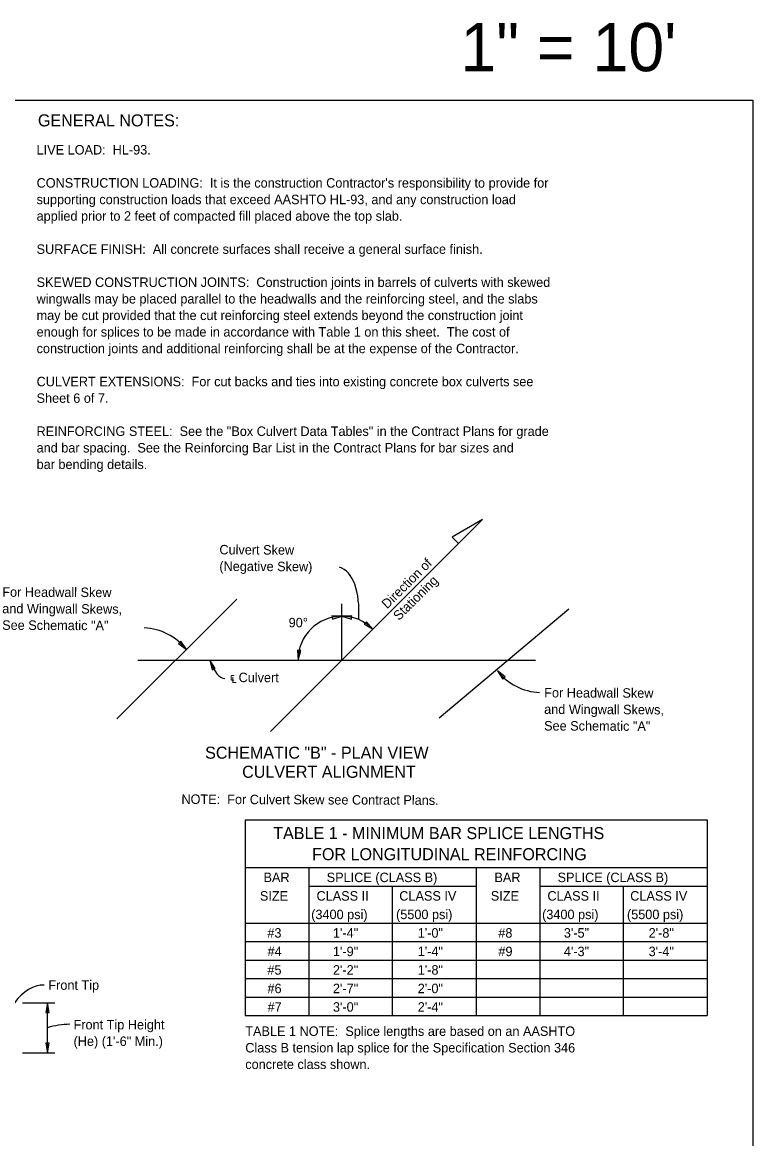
# Model space of a CAD drawing. Extents: x 6 to 291, y -45 to 111.
# Drawn here: x 101.7 to 159.9, y 22.3 to 111.3 of the extents above; entities that cross this region are included whole.
import ezdxf

# ---------------------------------------------------------------- set-up
doc = ezdxf.new("R2010")
doc.units = 0
for name, color, linetype in [('ActivePts-ConstElements', 7, 'Continuous'), ('AdhocPoint_dp', 7, 'Continuous'), ('CL_Minor', 7, 'Continuous'), ('Leader', 7, 'Continuous'), ('PlotBorder_dp', 7, 'Continuous'), ('SubStrConc', 7, 'Continuous'), ('Tables', 7, 'Continuous')]:
    doc.layers.add(name, color=color, linetype=linetype)

msp = doc.modelspace()

# ---------------------------------------------------------------- linework, layer by layer
at = {"layer": 'ActivePts-ConstElements'}
msp.add_lwpolyline([(5.513, 105.087), (159.887, 105.087), (159.887, 6.648), (5.513, 6.648)], close=True, dxfattribs=at)
at = {"layer": 'AdhocPoint_dp'}
msp.add_line((138.359, 71.665), (121.444, 54.75), dxfattribs=at)
msp.add_lwpolyline([(138.359, 71.665), (135.932, 70.255), (136.441, 69.747)], close=True, dxfattribs=at)
at = {"layer": 'CL_Minor'}
msp.add_line((110.873, 60.443), (142.578, 60.443), dxfattribs=at)
at = {"layer": 'Leader'}
msp.add_line((127.137, 60.443), (127.137, 64.939), dxfattribs=at)
for centre, radius, start, end in [((111.176, 58.492), 4.533, 38.2591, 87.41318), ((143.098, 62.394), 4.533, 218.2591, 267.41318), ((105.498, 25.127), 6.283, 90.41603, 107.01592)]:
    msp.add_arc(centre, radius, start, end, dxfattribs=at)
for centre, major_axis, ratio, start_param, end_param in [((125.161, 61.66), (-1.787, -6.198), 0.454139, 2.029538, 3.141593), ((117.704, 65.904), (-0.102, 6.91), 0.278379, 2.477956, 3.141593), ((103.368, 27.495), (-0.033, -7.044), 0.555933, 3.141593, 3.786656)]:
    msp.add_ellipse(centre, major_axis=major_axis, ratio=ratio, start_param=start_param, end_param=end_param, dxfattribs=at)
at = {"layer": 'PlotBorder_dp'}
for p, q in [((101.666, 33.134), (104.257, 33.134)), ((103.659, 29.134), (103.659, 33.134)), ((101.666, 29.134), (104.257, 29.134))]:
    msp.add_line(p, q, dxfattribs=at)
for points in [[(127.137, 63.944), (126.346, 63.988), (126.376, 63.725)], [(127.137, 63.944), (127.899, 63.726), (127.928, 63.989)], [(129.612, 62.918), (129.089, 63.513), (128.922, 63.308)], [(114.735, 61.299), (114.305, 61.965), (114.11, 61.786)], [(123.637, 60.443), (123.851, 61.206), (123.588, 61.234)], [(116.6, 60.443), (116.793, 59.675), (117.035, 59.782)], [(139.539, 59.587), (139.972, 58.924), (140.167, 59.104)], [(103.659, 33.134), (103.527, 32.353), (103.792, 32.353)], [(103.659, 29.134), (103.792, 29.915), (103.527, 29.915)]]:
    msp.add_lwpolyline(points, close=True, dxfattribs=at)
for start, end in [(90, 180), (45.00012, 90)]:
    msp.add_arc((127.137, 60.443), 3.5, start, end, dxfattribs=at)
at = {"layer": 'SubStrConc'}
for p, q in [((118.755, 65.319), (109.203, 55.768)), ((145.23, 64.5), (134.882, 55.817))]:
    msp.add_line(p, q, dxfattribs=at)
at = {"layer": 'Tables'}
for p, q in [((119.434, 47.722), (119.434, 32.1)), ((119.434, 47.722), (156.254, 47.722)), ((156.254, 47.722), (156.254, 32.1)), ((119.434, 43.908), (156.254, 43.908)), ((124.504, 43.908), (124.504, 32.1)), ((137.844, 43.908), (137.844, 32.1)), ((142.914, 43.908), (142.914, 32.1)), ((124.504, 42.432), (137.844, 42.432)), ((131.148, 42.432), (131.148, 32.1)), ((142.914, 42.432), (142.914, 32.1)), ((142.914, 42.432), (156.254, 42.432)), ((149.558, 42.432), (149.558, 32.1)), ((119.434, 39.48), (156.254, 39.48)), ((119.434, 38.004), (156.254, 38.004)), ((119.434, 36.528), (156.254, 36.528)), ((119.434, 35.052), (156.254, 35.052)), ((119.434, 33.576), (156.254, 33.576)), ((119.434, 32.1), (156.254, 32.1))]:
    msp.add_line(p, q, dxfattribs=at)

# ---------------------------------------------------------------- texts
at = {"layer": 'AdhocPoint_dp'}
for s, height, p in [('1" = 10\'', 3.84, (136.588, 107.409)), ('GENERAL NOTES:', 0.96, (102.901, 103.009)), ('LIVE LOAD:  HL-93.', 0.756, (102.795, 100.765)), ("CONSTRUCTION LOADING:  It is the construction Contractor's responsibility to provide for", 0.756, (102.795, 98.125)), ('supporting construction loads that exceed AASHTO HL-93, and any construction load', 0.756, (102.795, 96.805)), ('applied prior to 2 feet of compacted fill placed above the top slab.', 0.756, (102.795, 95.485)), ('SURFACE FINISH:  All concrete surfaces shall receive a general surface finish.', 0.756, (102.795, 92.845)), ('SKEWED CONSTRUCTION JOINTS:  Construction joints in barrels of culverts with skewed', 0.756, (102.795, 90.205)), ('wingwalls may be placed parallel to the headwalls and the reinforcing steel, and the slabs', 0.756, (102.795, 88.885)), ('may be cut provided that the cut reinforcing steel extends beyond the construction joint', 0.756, (102.795, 87.565)), ('enough for splices to be made in accordance with Table 1 on this sheet.  The cost of', 0.756, (102.795, 86.245)), ('construction joints and additional reinforcing shall be at the expense of the Contractor.', 0.756, (102.795, 84.925)), ('CULVERT EXTENSIONS:  For cut backs and ties into existing concrete box culverts see', 0.756, (102.795, 82.285)), ('Sheet 6 of 7.', 0.756, (102.795, 80.965)), ('REINFORCING STEEL:  See the "Box Culvert Data Tables" in the Contract Plans for grade', 0.756, (102.795, 78.325)), ('and bar spacing.  See the Reinforcing Bar List in the Contract Plans for bar sizes and', 0.756, (102.795, 77.005)), ('bar bending details.', 0.756, (102.795, 75.685)), ('SCHEMATIC "B" - PLAN VIEW', 0.96, (116.233, 52.588)), ('CULVERT ALIGNMENT', 0.96, (119.184, 51.064)), ('TABLE 1 - MINIMUM BAR SPLICE LENGTHS', 0.96, (121.661, 46.175)), ('FOR LONGITUDINAL REINFORCING', 0.96, (124.76, 44.495)), ('BAR', 0.756, (120.889, 42.748)), ('SPLICE (CLASS B)', 0.756, (125.924, 42.748)), ('BAR', 0.756, (139.299, 42.748)), ('SPLICE (CLASS B)', 0.756, (144.334, 42.748)), ('SIZE', 0.756, (120.598, 41.272)), ('CLASS II', 0.756, (125.114, 41.272)), ('CLASS IV', 0.756, (131.712, 41.272)), ('SIZE', 0.756, (139.008, 41.272)), ('CLASS II', 0.756, (143.524, 41.272)), ('CLASS IV', 0.756, (150.124, 41.272)), ('(3400 psi)', 0.756, (124.689, 39.796)), ('(5500 psi)', 0.756, (131.453, 39.796)), ('(3400 psi)', 0.756, (143.099, 39.796)), ('(5500 psi)', 0.756, (149.864, 39.796)), ('#3', 0.756, (121.194, 38.32)), ('1\'-4"', 0.756, (126.422, 38.32)), ('1\'-0"', 0.756, (133.184, 38.32)), ('#8', 0.756, (139.607, 38.32)), ('3\'-5"', 0.756, (144.832, 38.32)), ('2\'-8"', 0.756, (151.595, 38.32)), ('#4', 0.756, (121.21, 36.844)), ('1\'-9"', 0.756, (126.422, 36.844)), ('1\'-4"', 0.756, (133.184, 36.844)), ('#9', 0.756, (139.613, 36.844)), ('4\'-3"', 0.756, (144.832, 36.844)), ('3\'-4"', 0.756, (151.595, 36.844)), ('#5', 0.756, (121.198, 35.368)), ('2\'-2"', 0.756, (126.422, 35.368)), ('1\'-8"', 0.756, (133.184, 35.368)), ('Front Tip', 0.756, (103.735, 34.16)), ('#6', 0.756, (121.203, 33.892)), ('2\'-7"', 0.756, (126.422, 33.892)), ('2\'-0"', 0.756, (133.184, 33.892)), ('#7', 0.756, (121.212, 32.416)), ('3\'-0"', 0.756, (126.422, 32.416)), ('2\'-4"', 0.756, (133.184, 32.416)), ('Front Tip Height', 0.756, (105.743, 31.004)), ('TABLE 1 NOTE:  Splice lengths are based on an AASHTO', 0.756, (119.434, 30.484)), ('(He) (1\'-6" Min.)', 0.756, (105.743, 29.684)), ('Class B tension lap splice for the Specification Section 346', 0.756, (119.434, 29.164)), ('concrete class shown.', 0.756, (119.434, 27.844))]:
    msp.add_text(s, height=height, dxfattribs=at).set_placement(p)
for s, rotation, p in [('Culvert Skew', 359.76619, (117.371, 68.881)), ('Direction of', 44.76619, (130.749, 64.496)), ('(Negative Skew)', 359.76619, (117.366, 67.561)), ('Stationing', 44.76619, (131.678, 63.558)), ('For Headwall Skew', 359.76619, (100.061, 65.505)), ('and Wingwall Skews,', 359.76619, (100.056, 64.185)), ('See Schematic "A"', 359.76619, (100.051, 62.865)), ('90°', 359.76619, (122.89, 63.066)), ('℄ Culvert', 359.76619, (118.208, 58.697)), ('For Headwall Skew', 359.76619, (143.267, 57.478)), ('and Wingwall Skews,', 359.76619, (143.261, 56.158)), ('See Schematic "A"', 359.76619, (143.256, 54.838)), ('NOTE:  For Culvert Skew see Contract Plans.', 359.76619, (114.343, 48.986))]:
    msp.add_text(s, height=0.756, rotation=rotation, dxfattribs=at).set_placement(p)

doc.saveas('drawing.dxf')
